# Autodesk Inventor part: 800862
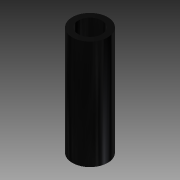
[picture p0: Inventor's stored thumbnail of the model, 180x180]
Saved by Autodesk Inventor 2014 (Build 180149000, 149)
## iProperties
Created: 2007-11
Part Number: 800862
Document SubType Name: Modeling
Designer: TH
Density: 1.425 g/cm^3
Mass: 0.523521 g
Surface Area: 7.18024 cm^2
Volume: 0.367383 cm^3
Material: Acetal Resin, Black
Description: WIRE CONNECTING TUBE
Appearance: Glossy - Black
Component Category: Fasteners
Author: TH
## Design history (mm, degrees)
sketch "Sketch1"
  geometry: C1 r 3.25 at (0, 0); C2 r 2.171 at (0, 0); 1 further point
  constraints: 2 centre point, 2 coincident
  dimensions: "d0" = 4.343 diameter of C2; "d1" = 6.5 diameter of C1
extrude "Extrusion1" new body sketch "Sketch1" stored distance "d2" = 20; taper "d3" = 0 deg
body "Solid1"
